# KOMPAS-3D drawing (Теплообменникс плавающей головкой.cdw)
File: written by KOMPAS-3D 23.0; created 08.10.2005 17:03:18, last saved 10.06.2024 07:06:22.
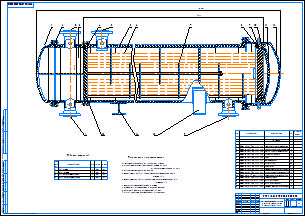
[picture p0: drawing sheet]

Sheet 1: A1, landscape

Document properties: Полное имя файла: G:\Учёба\Курсовое проектирование\Дипломы 2024\Алмаз\Для публикации ТПК\Теплообменникс плавающей головкой.cdw

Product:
- Part/product: (unnamed)  | designation УТЭК.18.02.09.ПП.00.00.000.ВО

Title block, sheet 1: Наименование: Кожухотрубный теплообменник / с плавающей головкой / Чертеж общего вида; designation: УТЭК.18.02.09.ПП.00.00.000.ВО; scale: 1:5; Количество листов документа: 1; Форматы листов документа: A1; stored path: C:\Documents and Settings\Администратор\Мои документы\Курсовой проект\Чертеж.cdw

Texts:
  Normal
  Техническая характеристика
  Аппарат предназначен для охлаждения бензина
  Производительность аппарата по нефти 21 кг/с
  Поверхность теплообмена 318 м2
  Температура на входе в аппарат масляной фракции  231␣С
  Symbol
  Температура на выходе из аппарата масляной фракции 65␣С
  Трубное пространство поток - нефть
  Межтрубное пространство - масляная фракция
  Давление в трубном пространстве 1,6 МПа
  Среда в аппарате малотоксичная, коррозионная
  Таблица штуцеров
  Обоз-
  наче-
  ние
  Кол.
  Dу, мм
  Pу, МПа
  Ввод нефти
  Вывод нефти
  Ввод масляной фракции
  Вывод масляной фракции
  Поз.
  Приме-
  чание
  Детали
  УТЭК 18.02.09 ПП.00.00.001
  Крышка камеры распределительной
  УТЭК 18.02.09 ПП.00.00.002
  Прокладка камеры распределительной
  УТЭК 18.02.09 ПП.00.00.003
  Камера распределительная
  УТЭК 18.02.09 ПП.00.00.004
  Прокладка кожуха
  УТЭК 18.02.09 ПП.00.00.005
  Кожух
  УТЭК 18.02.09 ПП.00.00.006
  Трубный пучок
  УТЭК 18.02.09 ПП.00.00.007
  Перегородка
  УТЭК 18.02.09 ПП.00.00.008
  Полукольцо
  УТЭК 18.02.09 ПП.00.00.009
  Решетка трубная подвижная
  УТЭК 18.02.09 ПП.00.00.010
  Прокладка плавающей головки
  УТЭК 18.02.09 ПП.00.00.011
  Крышка плавающей головки
  УТЭК 18.02.09 ПП.00.00.012
  Крышка кожуха
  УТЭК 18.02.09 ПП.00.00.013
  Опора подвижная
  УТЭК 18.02.09 ПП.00.00.014
  Опора неподвижная
  УТЭК 18.02.09 ПП.00.00.015
  Решетка трубная неподвижная
Dimensions and other numbers on the sheet: 1; 250; 4,0; 1,6; 2; 3; 4; 5; 6; 7; 24; 8; 9; 10; 11; 12; 13; 14; 15; 9000; 12480; 800; 1:5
